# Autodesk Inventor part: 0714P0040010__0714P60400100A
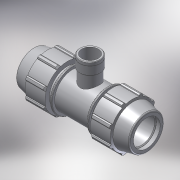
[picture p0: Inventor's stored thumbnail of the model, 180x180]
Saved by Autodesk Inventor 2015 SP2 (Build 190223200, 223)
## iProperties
Created: 2017-02
Part Number: 0714P0040010__0714P60400100A
Material: PVC-Piping
Description: PLASSON TEE FEMALE ADAPTOR WITHOUT STOP 40-1"
Document SubType Name: Modeling
Designer: KIM
Mass: 92.6774 g
Surface Area: 199.44 cm^2
Volume: 66.1981 cm^3
Density: 1.4 g/cm^3
Appearance: Smooth - White
Author: KIM
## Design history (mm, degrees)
derived "0714P0.ipt"
feature "Solid1::0714P0.ipt"
feature "Solid2::0714P0.ipt"
tag "TaggingFeature1"
body "Solid1"
other parameters: "d4" = 8.45833, "d5" = 24.36, "d7" = 82, "d11" = 3.38333, "d13" = 120 deg, "d15" = 12 deg, "d16" = 71.34, "d18" = 2, "d19" = 35 deg, "d20" = 17.5 deg, "d21" = 76.26, "d23" = 0, "d25" = 360 deg, "d27" = 1.64, "d33" = 0.8, "d42" = 36.54, "d43" = 2.46, "d46" = 1.2, "d68" = 6.09, "d72" = 61, "d76" = 30.291, "d80" = 0.90873, "d91" = 61.5, "d93" = 84, "d95" = 36, "d112" = 21, "d115" = 37.86375, "d116" = 135 deg, "d117" = 34.83465, "d118" = 203, "d119" = 36, "d121" = 0, "d122" = 25.2, "d124" = 0, "d128" = 0, "d129" = 4, "d130" = 6.3, "d131" = 0.3, "d132" = 0.3, "d133" = 37.86375, "E_" = 82, "A_" = 61, "l_" = 84, "l_2" = 21, "Rp_" = 30.291, "H_" = 203
